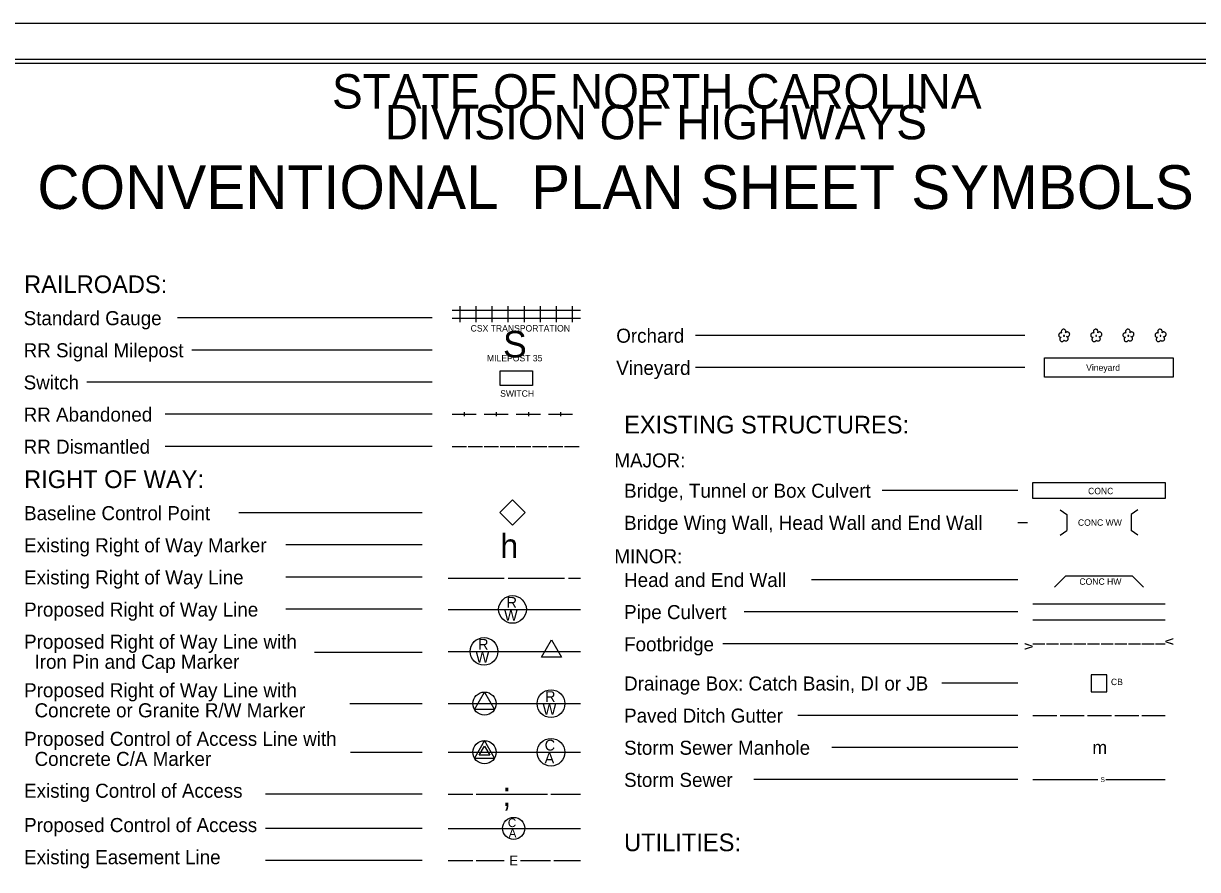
# Model space of a CAD drawing. Extents: x 10000 to 11684, y 10000 to 11100.
# Drawn here: x 10561 to 11292, y 10573 to 11100 of the extents above; entities that cross this region are included whole.
import ezdxf

# ---------------------------------------------------------------- set-up
doc = ezdxf.new("R2010")
doc.units = 0
for name, color, linetype in [('Default', 7, 'Continuous'), ('Sheet Cutting Line CELL', 7, 'Continuous'), ('Sheet Plot Border Inside CELL', 7, 'Continuous'), ('Sheet Plot Border Outside CELL', 7, 'Continuous'), ('Sheet Symbology CELL', 7, 'Continuous')]:
    doc.layers.add(name, color=color, linetype=linetype)

msp = doc.modelspace()

# ---------------------------------------------------------------- linework, layer by layer
at = {"layer": 'Default'}
msp.add_lwpolyline([(10857.82, 10795.56), (10865.64, 10803.38), (10873.47, 10795.56), (10865.64, 10787.73)], close=True, dxfattribs=at)
at = {"layer": 'Sheet Cutting Line CELL'}
msp.add_line((11684, 11100), (10000, 11100), dxfattribs=at)
at = {"layer": 'Sheet Plot Border Inside CELL'}
msp.add_lwpolyline([(10013, 10022.45), (11679.5, 10022.45), (11679.5, 11077.55), (10013, 11077.55)], close=True, dxfattribs=at)
at = {"layer": 'Sheet Plot Border Outside CELL'}
msp.add_lwpolyline([(10000, 10000), (11684, 10000), (11684, 11100), (10000, 11100)], close=True, dxfattribs=at)
at = {"layer": 'Sheet Symbology CELL'}
for p, q in [((10828, 10921.48), (10838, 10921.48)), ((10833, 10913.98), (10833, 10923.98)), ((10838, 10921.48), (10848, 10921.48)), ((10843, 10913.98), (10843, 10923.98)), ((10848, 10921.48), (10858, 10921.48)), ((10853, 10913.98), (10853, 10923.98)), ((10858, 10921.48), (10868, 10921.48)), ((10863, 10913.98), (10863, 10923.98)), ((10868, 10921.48), (10878, 10921.48)), ((10873, 10913.98), (10873, 10923.98)), ((10878, 10921.48), (10888, 10921.48)), ((10883, 10913.98), (10883, 10923.98)), ((10888, 10921.48), (10898, 10921.48)), ((10893, 10913.98), (10893, 10923.98)), ((10898, 10921.48), (10908, 10921.48)), ((10903, 10913.98), (10903, 10923.98)), ((10815.61, 10916.71), (10657.19, 10916.71)), ((10828, 10916.48), (10838, 10916.48)), ((10838, 10916.48), (10848, 10916.48)), ((10848, 10916.48), (10858, 10916.48)), ((10858, 10916.48), (10868, 10916.48)), ((10868, 10916.48), (10878, 10916.48)), ((10878, 10916.48), (10888, 10916.48)), ((10888, 10916.48), (10898, 10916.48)), ((10898, 10916.48), (10908, 10916.48)), ((11184.33, 10905.78), (10979.39, 10905.78)), ((10815.61, 10896.71), (10666.06, 10896.71)), ((11184.33, 10885.78), (10979.39, 10885.78)), ((10815.61, 10876.71), (10600.69, 10876.71)), ((10815.61, 10856.71), (10649.44, 10856.71)), ((10828, 10856.71), (10843, 10856.71)), ((10835.5, 10857.96), (10835.5, 10855.46)), ((10848, 10856.71), (10863, 10856.71)), ((10855.5, 10857.96), (10855.5, 10855.46)), ((10868, 10856.71), (10883, 10856.71)), ((10875.5, 10857.96), (10875.5, 10855.46)), ((10888, 10856.71), (10903, 10856.71)), ((10895.5, 10857.96), (10895.5, 10855.46)), ((10815.61, 10836.71), (10649.44, 10836.71)), ((10815.61, 10836.71), (10649.44, 10836.71)), ((10828, 10836.71), (10837, 10836.71)), ((10838, 10836.71), (10847, 10836.71)), ((10848, 10836.71), (10857, 10836.71)), ((10858, 10836.71), (10867, 10836.71)), ((10868, 10836.71), (10877, 10836.71)), ((10878, 10836.71), (10887, 10836.71)), ((10888, 10836.71), (10897, 10836.71)), ((10898, 10836.71), (10907, 10836.71)), ((11180.01, 10809.32), (11095.59, 10809.32)), ((11206.46, 10797.18), (11210.56, 10794.32)), ((11254.66, 10797.18), (11250.56, 10794.32)), ((10809.47, 10795.36), (10695.26, 10795.36)), ((11210.56, 10794.32), (11210.56, 10784.32)), ((11250.56, 10794.32), (11250.56, 10784.32)), ((11180.01, 10789.32), (11186, 10789.32)), ((11206.46, 10781.46), (11210.56, 10784.32)), ((11254.66, 10781.46), (11250.56, 10784.32)), ((10809.47, 10775.36), (10724.53, 10775.36)), ((10809.47, 10755.36), (10724.53, 10755.36)), ((10825.5, 10754.79), (10860.5, 10754.79)), ((10863, 10754.79), (10898, 10754.79)), ((10900.5, 10754.79), (10908, 10754.79)), ((11180.01, 10753.75), (11051.71, 10753.75)), ((11202.86, 10749.17), (11209.94, 10756.25)), ((11209.94, 10756.25), (11251.19, 10756.25)), ((11251.19, 10756.25), (11258.26, 10749.17)), ((11189.31, 10738.75), (11271.81, 10738.75)), ((10809.47, 10735.36), (10724.53, 10735.36)), ((10825.5, 10735.24), (10908, 10735.24)), ((11180.01, 10733.75), (11009.83, 10733.75)), ((11189.31, 10728.75), (11271.81, 10728.75)), ((11180.01, 10713.75), (10996.54, 10713.75)), ((11189.31, 10713.75), (11196.81, 10713.75)), ((11197.81, 10713.75), (11205.31, 10713.75)), ((11206.31, 10713.75), (11213.81, 10713.75)), ((11214.81, 10713.75), (11222.31, 10713.75)), ((11223.31, 10713.75), (11230.81, 10713.75)), ((11231.81, 10713.75), (11239.31, 10713.75)), ((11240.31, 10713.75), (11247.81, 10713.75)), ((11248.81, 10713.75), (11256.31, 10713.75)), ((11257.31, 10713.75), (11264.81, 10713.75)), ((11265.81, 10713.75), (11271.81, 10713.75)), ((10809.47, 10708.51), (10742.36, 10708.51)), ((10825.5, 10709.11), (10908, 10709.11)), ((10889.95, 10709.11), (10889.95, 10709.11)), ((11180.01, 10689.32), (11132.81, 10689.32)), ((10809.47, 10676.47), (10764.48, 10676.47)), ((10825.5, 10676.61), (10908, 10676.61)), ((10848.2, 10676.61), (10848.2, 10676.61)), ((11180.01, 10669.32), (11043.06, 10669.32)), ((11189.31, 10669.32), (11204.31, 10669.32)), ((11206.31, 10669.32), (11221.31, 10669.32)), ((11223.31, 10669.32), (11238.31, 10669.32)), ((11240.31, 10669.32), (11255.31, 10669.32)), ((11257.31, 10669.32), (11271.81, 10669.32)), ((10809.47, 10646.23), (10764.85, 10646.23)), ((10825.5, 10646.37), (10908, 10646.37)), ((10848.2, 10646.37), (10848.2, 10646.37)), ((11180.01, 10649.32), (11064.34, 10649.32)), ((11180.01, 10629.32), (11015.81, 10629.32)), ((11189.31, 10629.32), (11229.84, 10629.32)), ((11234.84, 10629.32), (11271.81, 10629.32)), ((10809.47, 10620.29), (10711.92, 10620.29)), ((10825.5, 10620.29), (10840.96, 10620.29)), ((10842.96, 10620.29), (10887.37, 10620.29)), ((10889.37, 10620.29), (10908, 10620.29)), ((10809.47, 10598.94), (10711.92, 10598.94)), ((10825.5, 10598.94), (10908, 10598.94)), ((10809.47, 10578.94), (10711.92, 10578.94)), ((10825.5, 10578.94), (10841.01, 10578.94)), ((10843.01, 10578.94), (10860.51, 10578.94)), ((10870.51, 10578.94), (10889.26, 10578.94)), ((10891.26, 10578.94), (10908, 10578.94))]:
    msp.add_line(p, q, dxfattribs=at)
for points in [[(11667, 11075), (10167, 11075), (10167, 10026.02), (11667, 10026.02)], [(10858, 10883.68), (10878, 10883.68), (10878, 10874.58), (10858, 10874.58)], [(10883.7, 10705.51), (10889.95, 10716.31), (10896.2, 10705.51)], [(11225.75, 10684.01), (11235.36, 10684.01), (11235.36, 10694.64), (11225.75, 10694.64)], [(10841.95, 10673.01), (10848.2, 10683.81), (10854.45, 10673.01)], [(10841.95, 10642.77), (10854.45, 10642.77), (10848.2, 10653.57)], [(10844.93, 10644.48), (10848.2, 10650.13), (10851.47, 10644.48)]]:
    msp.add_lwpolyline(points, close=True, dxfattribs=at)
for points in [[(11209.77, 10907.53), (11209.92, 10907.83), (11209.97, 10908.13), (11209.92, 10908.43), (11209.87, 10908.73), (11209.72, 10908.98), (11209.57, 10909.23), (11209.32, 10909.43), (11209.07, 10909.58), (11208.72, 10909.68), (11208.47, 10909.68), (11208.17, 10909.63), (11207.87, 10909.53), (11207.62, 10909.38), (11207.37, 10909.18), (11207.22, 10908.88), (11207.12, 10908.63), (11207.07, 10908.33), (11207.07, 10908.03), (11207.12, 10907.73), (11207.27, 10907.48), (11207.47, 10907.18), (11207.22, 10907.33), (11206.92, 10907.38), (11206.62, 10907.38), (11206.37, 10907.28), (11206.12, 10907.18), (11205.87, 10906.98), (11205.67, 10906.78), (11205.52, 10906.53), (11205.47, 10906.28), (11205.42, 10905.93), (11205.47, 10905.68), (11205.57, 10905.43), (11205.77, 10905.18), (11205.92, 10904.98), (11206.17, 10904.83), (11206.47, 10904.68), (11206.72, 10904.63), (11207.02, 10904.63), (11206.77, 10904.53), (11206.52, 10904.33), (11206.37, 10904.13), (11206.27, 10903.83), (11206.17, 10903.53), (11206.17, 10903.28), (11206.22, 10902.98), (11206.37, 10902.73), (11206.52, 10902.48), (11206.72, 10902.28), (11206.97, 10902.13), (11207.22, 10902.03), (11207.52, 10902.03), (11207.82, 10902.03), (11208.07, 10902.08), (11208.32, 10902.28), (11208.57, 10902.43), (11208.82, 10902.88)], [(11208.82, 10902.88), (11209.42, 10902.53), (11209.72, 10902.43), (11210.02, 10902.38), (11210.32, 10902.43), (11210.57, 10902.53), (11210.82, 10902.68), (11211.07, 10902.88), (11211.22, 10903.13), (11211.32, 10903.38), (11211.42, 10903.68), (11211.37, 10903.98), (11211.32, 10904.28), (11211.12, 10904.58), (11210.97, 10904.78), (11210.72, 10904.93), (11210.42, 10905.08), (11210.72, 10905.03), (11211.07, 10905.03), (11211.32, 10905.13), (11211.62, 10905.28), (11211.87, 10905.43), (11212.07, 10905.68), (11212.22, 10905.98), (11212.27, 10906.28), (11212.32, 10906.58), (11212.27, 10906.88), (11212.17, 10907.18), (11211.97, 10907.43), (11211.72, 10907.68), (11211.47, 10907.83), (11211.17, 10907.93), (11210.87, 10907.98), (11210.57, 10907.98), (11210.27, 10907.88), (11210.02, 10907.73), (11209.77, 10907.53)], [(11229.77, 10907.53), (11229.92, 10907.83), (11229.97, 10908.13), (11229.92, 10908.43), (11229.87, 10908.73), (11229.72, 10908.98), (11229.57, 10909.23), (11229.32, 10909.43), (11229.07, 10909.58), (11228.72, 10909.68), (11228.47, 10909.68), (11228.17, 10909.63), (11227.87, 10909.53), (11227.62, 10909.38), (11227.37, 10909.18), (11227.22, 10908.88), (11227.12, 10908.63), (11227.07, 10908.33), (11227.07, 10908.03), (11227.12, 10907.73), (11227.27, 10907.48), (11227.47, 10907.18), (11227.22, 10907.33), (11226.92, 10907.38), (11226.62, 10907.38), (11226.37, 10907.28), (11226.12, 10907.18), (11225.87, 10906.98), (11225.67, 10906.78), (11225.52, 10906.53), (11225.47, 10906.28), (11225.42, 10905.93), (11225.47, 10905.68), (11225.57, 10905.43), (11225.77, 10905.18), (11225.92, 10904.98), (11226.17, 10904.83), (11226.47, 10904.68), (11226.72, 10904.63), (11227.02, 10904.63), (11226.77, 10904.53), (11226.52, 10904.33), (11226.37, 10904.13), (11226.27, 10903.83), (11226.17, 10903.53), (11226.17, 10903.28), (11226.22, 10902.98), (11226.37, 10902.73), (11226.52, 10902.48), (11226.72, 10902.28), (11226.97, 10902.13), (11227.22, 10902.03), (11227.52, 10902.03), (11227.82, 10902.03), (11228.07, 10902.08), (11228.32, 10902.28), (11228.57, 10902.43), (11228.82, 10902.88)], [(11228.82, 10902.88), (11229.42, 10902.53), (11229.72, 10902.43), (11230.02, 10902.38), (11230.32, 10902.43), (11230.57, 10902.53), (11230.82, 10902.68), (11231.07, 10902.88), (11231.22, 10903.13), (11231.32, 10903.38), (11231.42, 10903.68), (11231.37, 10903.98), (11231.32, 10904.28), (11231.12, 10904.58), (11230.97, 10904.78), (11230.72, 10904.93), (11230.42, 10905.08), (11230.72, 10905.03), (11231.07, 10905.03), (11231.32, 10905.13), (11231.62, 10905.28), (11231.87, 10905.43), (11232.07, 10905.68), (11232.22, 10905.98), (11232.27, 10906.28), (11232.32, 10906.58), (11232.27, 10906.88), (11232.17, 10907.18), (11231.97, 10907.43), (11231.72, 10907.68), (11231.47, 10907.83), (11231.17, 10907.93), (11230.87, 10907.98), (11230.57, 10907.98), (11230.27, 10907.88), (11230.02, 10907.73), (11229.77, 10907.53)], [(11249.77, 10907.53), (11249.92, 10907.83), (11249.97, 10908.13), (11249.92, 10908.43), (11249.87, 10908.73), (11249.72, 10908.98), (11249.57, 10909.23), (11249.32, 10909.43), (11249.07, 10909.58), (11248.72, 10909.68), (11248.47, 10909.68), (11248.17, 10909.63), (11247.87, 10909.53), (11247.62, 10909.38), (11247.37, 10909.18), (11247.22, 10908.88), (11247.12, 10908.63), (11247.07, 10908.33), (11247.07, 10908.03), (11247.12, 10907.73), (11247.27, 10907.48), (11247.47, 10907.18), (11247.22, 10907.33), (11246.92, 10907.38), (11246.62, 10907.38), (11246.37, 10907.28), (11246.12, 10907.18), (11245.87, 10906.98), (11245.67, 10906.78), (11245.52, 10906.53), (11245.47, 10906.28), (11245.42, 10905.93), (11245.47, 10905.68), (11245.57, 10905.43), (11245.77, 10905.18), (11245.92, 10904.98), (11246.17, 10904.83), (11246.47, 10904.68), (11246.72, 10904.63), (11247.02, 10904.63), (11246.77, 10904.53), (11246.52, 10904.33), (11246.37, 10904.13), (11246.27, 10903.83), (11246.17, 10903.53), (11246.17, 10903.28), (11246.22, 10902.98), (11246.37, 10902.73), (11246.52, 10902.48), (11246.72, 10902.28), (11246.97, 10902.13), (11247.22, 10902.03), (11247.52, 10902.03), (11247.82, 10902.03), (11248.07, 10902.08), (11248.32, 10902.28), (11248.57, 10902.43), (11248.82, 10902.88)], [(11248.82, 10902.88), (11249.42, 10902.53), (11249.72, 10902.43), (11250.02, 10902.38), (11250.32, 10902.43), (11250.57, 10902.53), (11250.82, 10902.68), (11251.07, 10902.88), (11251.22, 10903.13), (11251.32, 10903.38), (11251.42, 10903.68), (11251.37, 10903.98), (11251.32, 10904.28), (11251.12, 10904.58), (11250.97, 10904.78), (11250.72, 10904.93), (11250.42, 10905.08), (11250.72, 10905.03), (11251.07, 10905.03), (11251.32, 10905.13), (11251.62, 10905.28), (11251.87, 10905.43), (11252.07, 10905.68), (11252.22, 10905.98), (11252.27, 10906.28), (11252.32, 10906.58), (11252.27, 10906.88), (11252.17, 10907.18), (11251.97, 10907.43), (11251.72, 10907.68), (11251.47, 10907.83), (11251.17, 10907.93), (11250.87, 10907.98), (11250.57, 10907.98), (11250.27, 10907.88), (11250.02, 10907.73), (11249.77, 10907.53)], [(11269.77, 10907.53), (11269.92, 10907.83), (11269.97, 10908.13), (11269.92, 10908.43), (11269.87, 10908.73), (11269.72, 10908.98), (11269.57, 10909.23), (11269.32, 10909.43), (11269.07, 10909.58), (11268.72, 10909.68), (11268.47, 10909.68), (11268.17, 10909.63), (11267.87, 10909.53), (11267.62, 10909.38), (11267.37, 10909.18), (11267.22, 10908.88), (11267.12, 10908.63), (11267.07, 10908.33), (11267.07, 10908.03), (11267.12, 10907.73), (11267.27, 10907.48), (11267.47, 10907.18), (11267.22, 10907.33), (11266.92, 10907.38), (11266.62, 10907.38), (11266.37, 10907.28), (11266.12, 10907.18), (11265.87, 10906.98), (11265.67, 10906.78), (11265.52, 10906.53), (11265.47, 10906.28), (11265.42, 10905.93), (11265.47, 10905.68), (11265.57, 10905.43), (11265.77, 10905.18), (11265.92, 10904.98), (11266.17, 10904.83), (11266.47, 10904.68), (11266.72, 10904.63), (11267.02, 10904.63), (11266.77, 10904.53), (11266.52, 10904.33), (11266.37, 10904.13), (11266.27, 10903.83), (11266.17, 10903.53), (11266.17, 10903.28), (11266.22, 10902.98), (11266.37, 10902.73), (11266.52, 10902.48), (11266.72, 10902.28), (11266.97, 10902.13), (11267.22, 10902.03), (11267.52, 10902.03), (11267.82, 10902.03), (11268.07, 10902.08), (11268.32, 10902.28), (11268.57, 10902.43), (11268.82, 10902.88)], [(11268.82, 10902.88), (11269.42, 10902.53), (11269.72, 10902.43), (11270.02, 10902.38), (11270.32, 10902.43), (11270.57, 10902.53), (11270.82, 10902.68), (11271.07, 10902.88), (11271.22, 10903.13), (11271.32, 10903.38), (11271.42, 10903.68), (11271.37, 10903.98), (11271.32, 10904.28), (11271.12, 10904.58), (11270.97, 10904.78), (11270.72, 10904.93), (11270.42, 10905.08), (11270.72, 10905.03), (11271.07, 10905.03), (11271.32, 10905.13), (11271.62, 10905.28), (11271.87, 10905.43), (11272.07, 10905.68), (11272.22, 10905.98), (11272.27, 10906.28), (11272.32, 10906.58), (11272.27, 10906.88), (11272.17, 10907.18), (11271.97, 10907.43), (11271.72, 10907.68), (11271.47, 10907.83), (11271.17, 10907.93), (11270.87, 10907.98), (11270.57, 10907.98), (11270.27, 10907.88), (11270.02, 10907.73), (11269.77, 10907.53)], [(11208.92, 10905.78), (11208.77, 10905.78), (11208.67, 10905.73), (11208.57, 10905.68), (11208.57, 10905.53), (11208.57, 10905.43), (11208.67, 10905.33), (11208.82, 10905.33), (11208.92, 10905.33), (11209.02, 10905.43), (11209.07, 10905.58), (11209.02, 10905.68), (11208.92, 10905.78)], [(11228.92, 10905.78), (11228.77, 10905.78), (11228.67, 10905.73), (11228.57, 10905.68), (11228.57, 10905.53), (11228.57, 10905.43), (11228.67, 10905.33), (11228.82, 10905.33), (11228.92, 10905.33), (11229.02, 10905.43), (11229.07, 10905.58), (11229.02, 10905.68), (11228.92, 10905.78)], [(11248.92, 10905.78), (11248.77, 10905.78), (11248.67, 10905.73), (11248.57, 10905.68), (11248.57, 10905.53), (11248.57, 10905.43), (11248.67, 10905.33), (11248.82, 10905.33), (11248.92, 10905.33), (11249.02, 10905.43), (11249.07, 10905.58), (11249.02, 10905.68), (11248.92, 10905.78)], [(11268.92, 10905.78), (11268.77, 10905.78), (11268.67, 10905.73), (11268.57, 10905.68), (11268.57, 10905.53), (11268.57, 10905.43), (11268.67, 10905.33), (11268.82, 10905.33), (11268.92, 10905.33), (11269.02, 10905.43), (11269.07, 10905.58), (11269.02, 10905.68), (11268.92, 10905.78)], [(11196.72, 10891.78), (11276.72, 10891.78), (11276.72, 10879.78), (11196.72, 10879.78), (11196.72, 10891.78)], [(11189.31, 10814.32), (11271.81, 10814.32), (11271.81, 10804.32), (11189.31, 10804.32), (11189.31, 10814.32)]]:
    msp.add_lwpolyline(points, dxfattribs=at)
for centre, radius in [((10865.62, 10735.24), 8.61), ((10847.92, 10709.11), 8.61), ((10848.2, 10676.61), 7.2), ((10889.59, 10676.61), 8.61), ((10848.2, 10646.36), 7.2), ((10889.59, 10646.37), 8.61), ((10866.37, 10598.94), 6.89)]:
    msp.add_circle(centre, radius, dxfattribs=at)

# ---------------------------------------------------------------- texts
for s, height, p in [('STATE OF NORTH CAROLINA', 21.419, (10753.3, 11047.04)), ('DIVISION OF HIGHWAYS', 21.419, (10786.15, 11027.87)), ('CONVENTIONAL  PLAN SHEET SYMBOLS', 27.2003, (10569.99, 10984.55)), ('RAILROADS:', 11, (10561.72, 10932.16)), ('Standard Gauge', 8.75, (10561.44, 10912.19)), ('S', 16.5, (10859.76, 10892.09)), ('Orchard', 8.75, (10930.17, 10901.26)), ('RR Signal Milepost', 8.75, (10561.44, 10892.19)), ('Vineyard', 8.75, (10930.17, 10881.26)), ('Switch', 8.75, (10561.44, 10872.19)), ('RR Abandoned', 8.75, (10561.44, 10852.19)), ('EXISTING STRUCTURES:', 11, (10935.05, 10844.77)), ('RR Dismantled', 8.75, (10561.44, 10832.19)), ('MAJOR:', 8.75, (10929.02, 10823.65)), ('RIGHT OF WAY:', 11, (10561.72, 10810.81)), ('Bridge, Tunnel or Box Culvert', 8.75, (10935.05, 10804.77)), ('CONC', 4, (11223.75, 10806.96)), ('Baseline Control Point', 8.75, (10561.72, 10790.81)), ('Bridge Wing Wall, Head Wall and End Wall', 8.75, (10935.05, 10784.77)), ('h', 15, (10858.01, 10767.29)), ('Existing Right of Way Marker', 8.75, (10561.72, 10770.81)), ('MINOR:', 8.75, (10929.02, 10763.95)), ('Existing Right of Way Line', 8.75, (10561.72, 10750.81)), ('Head and End Wall', 8.75, (10935.05, 10749.2)), ('Proposed Right of Way Line', 8.75, (10561.72, 10730.81)), ('R', 6.75, (10861.91, 10736.25)), ('W', 6.75, (10860.37, 10728.3)), ('Pipe Culvert', 8.75, (10935.05, 10729.21)), ('Proposed Right of Way Line with', 8.75, (10561.72, 10710.81)), ('R', 6.75, (10844.21, 10710.12)), ('Footbridge', 8.75, (10935.06, 10709.21)), ('  Iron Pin and Cap Marker', 8.75, (10561.72, 10698.31)), ('W', 6.75, (10842.67, 10702.17)), ('Proposed Right of Way Line with', 8.75, (10561.72, 10680.59)), ('Drainage Box: Catch Basin, DI or JB', 8.75, (10935.06, 10684.78)), ('R', 6.75, (10885.89, 10677.62)), ('  Concrete or Granite R/W Marker', 8.75, (10561.72, 10668.09)), ('W', 6.75, (10884.35, 10669.67)), ('Paved Ditch Gutter', 8.75, (10935.06, 10664.77)), ('Proposed Control of Access Line with', 8.75, (10561.72, 10650.34)), ('C', 6.75, (10885.63, 10647.38)), ('Storm Sewer Manhole', 8.75, (10935.06, 10644.77)), ('m', 8.25, (11226.44, 10645.19)), ('  Concrete C/A Marker', 8.75, (10561.72, 10637.84)), ('A', 6.75, (10885.57, 10639.43)), ('Storm Sewer', 8.75, (10935.06, 10624.77)), ('S', 3, (11231.44, 10627.82)), ('Existing Control of Access', 8.75, (10561.72, 10618.02)), (';', 15, (10859.25, 10612.79)), ('Proposed Control of Access', 8.75, (10561.72, 10596.67)), ('C', 5.4, (10862.71, 10599.75)), ('A', 5.4, (10863.25, 10593.26)), ('UTILITIES:', 11, (10935.05, 10584.77)), ('Existing Easement Line', 8.75, (10561.72, 10576.67)), ('E', 6, (10863.71, 10575.94))]:
    msp.add_text(s, height=height, dxfattribs=at).set_placement(p)
for s, height, rotation, p in [('CSX TRANSPORTATION', 4, 360, (10839.56, 10908.24)), ('MILEPOST 35', 4, 360, (10849.75, 10889.66)), ('Vineyard', 4, 0.00002, (11222.55, 10883.78)), ('SWITCH', 4, 360, (10857.95, 10867.66)), ('CONC WW', 4, 0.00002, (11217.44, 10787.32)), ('CONC HW', 4, 360, (11218.36, 10750.59)), ('v', 6.6, 270.24085, (11271.8, 10717.49)), ('v', 6.6, 89.75915, (11189.3, 10710.01)), ('CB', 4, 360, (11238, 10688.14))]:
    msp.add_text(s, height=height, rotation=rotation, dxfattribs=at).set_placement(p)

doc.saveas('drawing.dxf')
